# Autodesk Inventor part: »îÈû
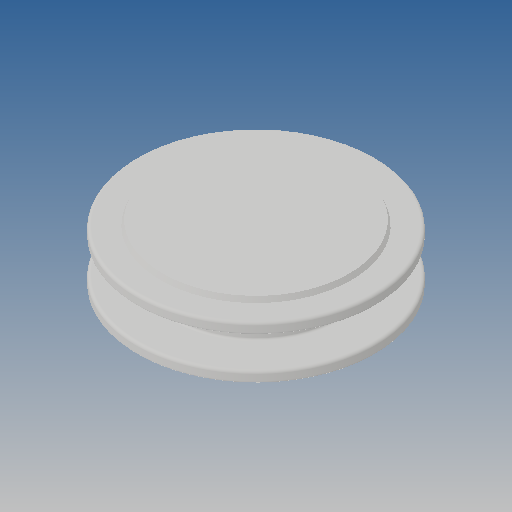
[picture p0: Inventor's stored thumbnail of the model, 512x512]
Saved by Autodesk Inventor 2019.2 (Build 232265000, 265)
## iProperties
Created: 2013-07
Part Number: »îÈû
Material: Ogólny
Document SubType Name: Modeling
Designer: CADENGINEERING4
Density: 1 g/cm^3
Appearance: Domyślna
Author: CADENGINEERING4
Revision Number: ÈÎºÎ
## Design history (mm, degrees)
feature "Ðý×ª1"
node "Bryła1"
